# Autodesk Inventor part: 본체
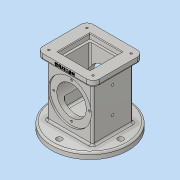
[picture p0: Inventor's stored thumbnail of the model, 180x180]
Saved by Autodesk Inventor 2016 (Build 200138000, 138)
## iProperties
Created: 2018-10
Part Number: 본체
Material: 알루미늄 6061
Document SubType Name: Modeling
Designer: Administrator
Density: 2.7 g/cm^3
Appearance: 알루미늄 - 평지
Author: Administrator
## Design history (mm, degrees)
sketch "스케치1"
  geometry: C1 r 62.5 at (0, 0); 1 further point
  constraints: 1 centre point, 1 coincident
  dimensions: "d0" = 125 diameter of C1
extrude "돌출1" new body sketch "스케치1" distance "d1" = 10; taper "d2" = 0 deg
sketch "스케치2"
  geometry: L1 (-37, 33)-(37, 33); L2 (37, 33)-(37, -33); L3 (37, -33)-(-37, -33); L4 (-37, -33)-(-37, 33); L5 (-37, 33)-(37, -33); L6 (37, 33)-(-37, -33); 1 further point
  constraints: 12 end point, 2 midpoint, 2 parallel, 1 horizontal, 1 perpendicular
  dimensions: "d3" = 74 distance of L1.start L1.end; "d4" = 66 distance of L1.end L2.end
extrude "돌출2" join sketch "스케치2" distance "d5" = 88; taper "d6" = 0 deg
sketch "스케치3"
  geometry: L1 (-46, 41)-(46, 41); L2 (46, 41)-(46, -41); L3 (46, -41)-(-46, -41); L4 (-46, -41)-(-46, 41); L5 (-46, 41)-(46, -41); L6 (46, 41)-(-46, -41); 1 further point
  constraints: 12 end point, 2 midpoint, 2 parallel, 1 horizontal, 1 perpendicular
  dimensions: "d7" = 92 distance of L1.start L1.end; "d8" = 82 distance of L1.end L2.end
extrude "돌출3" join sketch "스케치3" distance "d9" = 10; taper "d10" = 0 deg
sketch "스케치4"
  geometry: L1 (-26, -26)-(26, -26); L2 (26, -26)-(26, 26); L3 (26, 26)-(-26, 26); L4 (-26, 26)-(-26, -26); L5 (-26, -26)-(26, 26); L6 (26, -26)-(-26, 26); 1 further point
  constraints: 12 end point, 2 midpoint, 2 parallel, 1 horizontal, 1 perpendicular
  dimensions: "d11" = 52 distance of L3.end L1.start; "d12" = 52 distance of L2.end L3.end
extrude "돌출4" cut sketch "스케치4" distance "d13" = 8; taper "d14" = 0 deg
sketch "스케치5"
  geometry: L1 (-22, 22)-(22, 22); L2 (22, 22)-(22, -22); L3 (22, -22)-(-22, -22); L4 (-22, -22)-(-22, 22); L5 (-22, 22)-(22, -22); L6 (22, 22)-(-22, -22); 1 further point
  constraints: 12 end point, 2 midpoint, 2 parallel, 1 horizontal, 1 perpendicular
  dimensions: "d15" = 44 distance of L1.end L2.end; "d16" = 44 distance of L1.start L1.end
extrude "돌출5" cut sketch "스케치5" distance "d17" = 74; taper "d18" = 0 deg
sketch "스케치6"
  geometry: L1 (-33, 10)-(-33, 98) reference; L2 (-33, 54)-(33, 54); L3 (33, 10)-(33, 98) reference; L4 (-33, 54)-(-33, 89); L5 (-33, 89)-(-30, 89); L6 (-30, 89)-(-30, 78); L7 (-30, 78)-(30, 78); L8 (30, 78)-(30, 89); L9 (30, 89)-(33, 89); L10 (33, 89)-(33, 54); 1 further point
  constraints: 16 end point, 4 perpendicular, 4 point on line, 2 midpoint, 1 horizontal
  dimensions: "d19" = 70 diameter of L5 L2; "d20" = 48 diameter of L7 L2; "d21" = 3 distance between parallel lines of L6 L1; "d22" = 3 distance between parallel lines of L3 L8
revolve "회전1" sketch "스케치6" stored, may be unused: angle "d23" = 90 deg
sketch "스케치7"
  geometry: L1 (0, 0)-(0, 56.813); L2 (-62.5, 0)-(62.5, 0) reference; L3 (0, 18)-(22.309, 18); L4 (25.263, 15.521)-(28, 0); L5 (0, 0)-(28, 0); A1 r 3 centre (22.309, 15) between (25.263, 15.521) and (22.309, 18)
  constraints: 8 end point, 2 point on circle, 2 point on line, 2 tangent, 1 centre point, 1 collinear, 1 horizontal, 1 vertical
  dimensions: "d26" = 80 deg angle of L2 L4; "d27" = 18 distance between parallel lines of L2 L3; "d29" = 56 diameter of L4.end L1; "d30" = 3 radius of A1
revolve "회전2" sketch "스케치7" stored, may be unused: angle "d31" = 90 deg
sketch "스케치8"
  geometry: C1 r 22.309 at (0, 0) reference; C2 r 4.5 at (0, 50); C3 r 4.5 at (-50, 0); C4 r 4.5 at (0, -50); C5 r 4.5 at (50, 0); A1 r 50 centre (0, 0) between (0, 50) and (-50, 0); 1 further point
  constraints: 5 centre point, 4 point on circle, 2 horizontal alignment, 2 vertical alignment, 1 coincident
  dimensions: "d32" = 100 diameter of A1; "d33" = 9 diameter of C5; "d34" = 9 diameter of C2; "d35" = 9 diameter of C3; "d36" = 9 diameter of C4
extrude "돌출6" cut sketch "스케치8" distance "d37" = 10; taper "d38" = 0 deg
fillet "모깎기1" dims "d39" = 3
fillet "모깎기2" dims "d40" = 10
chamfer "모따기1" distance "d41" = 1; stored, may be unused: second distance "d42" = 2, angle "d43" = 45 deg
sketch "스케치9"
  geometry: L1 (-36, 31)-(36, 31); L2 (36, 31)-(36, -31); L3 (36, -31)-(-36, -31); L4 (-36, -31)-(-36, 31); L5 (-36, 31)-(36, -31); L6 (36, 31)-(-36, -31); 6 further points
  constraints: 12 end point, 5 coincident, 2 midpoint, 2 parallel, 1 horizontal, 1 perpendicular
  dimensions: "d44" = 72 distance of L1.start L1.end; "d46" = 62 distance of L1.end L2.end
hole "구멍1" sketch "스케치9" at (36, 31), (36, -31), (-36, -31), (-36, 31) diameter "d47" = 3.242; stored, may be unused: countersink angle "d51" = 90 deg, drill point angle "d53" = 118 deg; dims "d48" = 4, "d49" = 4, "d50" = 2, "d52" = 6
fillet "모깎기3" dims "d54" = 3
sketch "스케치12" dims "d56" = 58
  geometry: L1 (-37, -44)-(-37, 44) reference; 4 further points
  constraints: 3 vertical alignment, 1 horizontal alignment, 1 midpoint, 2 other
hole "구멍2" sketch "스케치12" at (0, 29) diameter "d57" = 3.242; stored, may be unused: countersink angle "d61" = 90 deg, drill point angle "d63" = 118 deg; dims "d58" = 4, "d59" = 4, "d60" = 2, "d62" = 6
sketch "스케치13"
  geometry: L1 (10, -29.5)-(10, 95.5) reference; L2 (10, 33)-(-115.764, 33); 2 further points
  constraints: 2 end point, 2 point on line, 1 horizontal
  dimensions: "d67" = 37 distance from line of L1 point (-27, 33); "d68" = 43 distance of point (-70, 33) point (-27, 33)
hole "구멍3" sketch "스케치13" at (-27, 33), (-70, 33) diameter "d69" = 4.134; stored, may be unused: countersink angle "d73" = 90 deg, drill point angle "d75" = 118 deg; dims "d70" = 10, "d71" = 4, "d72" = 2, "d74" = 20
fillet "모깎기4" dims "d76" = 3
fillet "모깎기5" dims "d77" = 3
fillet "모깎기6" dims "d78" = 3
node "작업 평면2"
sketch "스케치15"
  geometry: 1 further point
sketch "스케치16"
  geometry: L1 (-36, 108)-(36, 108) reference; L2 (-46, 108)-(-46, 101) reference; 3 further points
  constraints: 1 coincident, 1 other
  dimensions: "d83" = 4 distance from line of L1 point (0, 104); "d84" = 46 distance from line of L2 point (0, 104)
feature "엠보싱1" sketch "스케치16" dims "d1" = 10, "d85" = 0.5, "d86" = 0
fillet "모깎기7" dims "d87" = 3
node "솔리드1"
pattern_circular "원형 패턴1" dims angle "d65" = 360 deg
mirror "대칭1"
